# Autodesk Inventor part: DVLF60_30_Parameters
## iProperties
Created: 2010-03
Part Number: DVLF60_30_Parameters
Document SubType Name: Modeling
Designer: TB
Density: 1 g/cm^3
Slaglengde: 100.000 mm
Vinkel_Plussport: 0.00 deg
Vinkel_Minusport: 0.00 deg
Forlengelse_rør: 0.000 mm
Author: TB
